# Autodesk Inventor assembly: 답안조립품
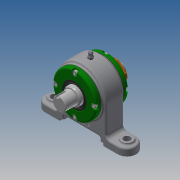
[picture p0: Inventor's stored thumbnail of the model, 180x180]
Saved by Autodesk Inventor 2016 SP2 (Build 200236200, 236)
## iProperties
Created: 2019-05
Part Number: 답안조립품
Document SubType Name: Assembly
Designer: EZ
Author: EZ
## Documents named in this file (13)
- Y:\490504V1044 이택근\답안조립품.iam
- Y:\490504V1044 이택근\본체.ipt
- Y:\490504V1044 이택근\앵귤러 볼 베어링 7205.ipt
- Y:\490504V1044 이택근\축.ipt
- Y:\490504V1044 이택근\칼라.ipt
- Y:\490504V1044 이택근\베어링너트.ipt
- Y:\490504V1044 이택근\커버.ipt
- Y:\490504V1044 이택근\개스킷.ipt
- Y:\490504V1044 이택근\오일 실 28 40 5 B.ipt
- Y:\490504V1044 이택근\볼트 M4.ipt
- Y:\490504V1044 이택근\그리스니플 M6.ipt
- 그리스니플  M6.ipt
- Y:\490504V1044 이택근\그리스니플개스킷.ipt
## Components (4 placed, 3 different names)
1. 개스킷:1
2. 개스킷:2
3. 그리스니플  M6:1
4. 그리스니플개스킷:1
